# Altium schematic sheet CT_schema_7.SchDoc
size 145 x 123 mm
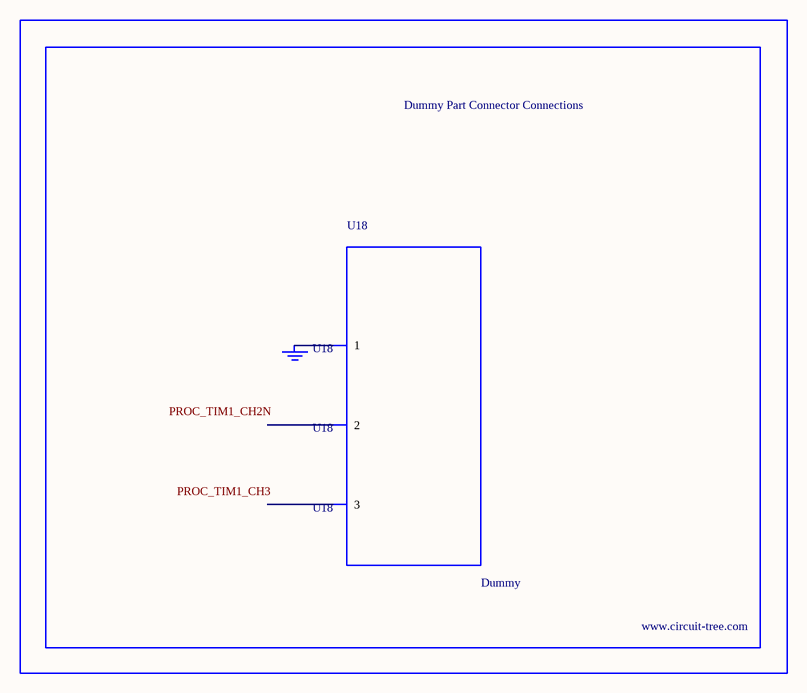
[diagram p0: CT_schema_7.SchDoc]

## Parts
BORDER6  (no value)
GND_INSTANCE_6_0  (no value)
U18  Dummy  [DUMMY_PACKAGE_149]

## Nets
NetGND_INSTANCE_6_0_0: GND_INSTANCE_6_0.0(GND) U18.1

Not connected (* = marked no-connect by the designer): U18 2 3

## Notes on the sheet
- Labels drawn without touching a wire or pin: PROC_TIM1_CH2N, PROC_TIM1_CH3

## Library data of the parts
BORDER6 = BORDER_PAGE6
GND_INSTANCE_6_0 = GND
